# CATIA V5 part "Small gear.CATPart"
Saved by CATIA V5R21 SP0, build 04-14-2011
Part number: Part3
Bounding box of the stored display mesh (mm): x -20 to 20, y -20 to 20, z 0 to 10
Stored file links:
  D:\CATIA V5R21 E-RESOURCES\CATIA-V5R21\catia-v5r21-prt\c16-catia-v5r20-prt\Gear Joint-(16-53)\CAT_V5R21_Small gear.CATPart
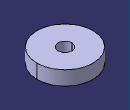
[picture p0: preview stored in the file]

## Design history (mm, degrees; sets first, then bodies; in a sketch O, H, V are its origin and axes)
Body1 (main body)
  Sketch1 on xy-plane, origin (0, 0, 0), H (1, 0, 0), V (0, 1, 0)
    circle A1 centre (0, 0) radius 20
    circle A2 centre (0, 0) radius 5
    radius A1 = 20
    radius A2 = 5
  Pad1: profile Sketch1, direction (0, 0, 1), length 10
